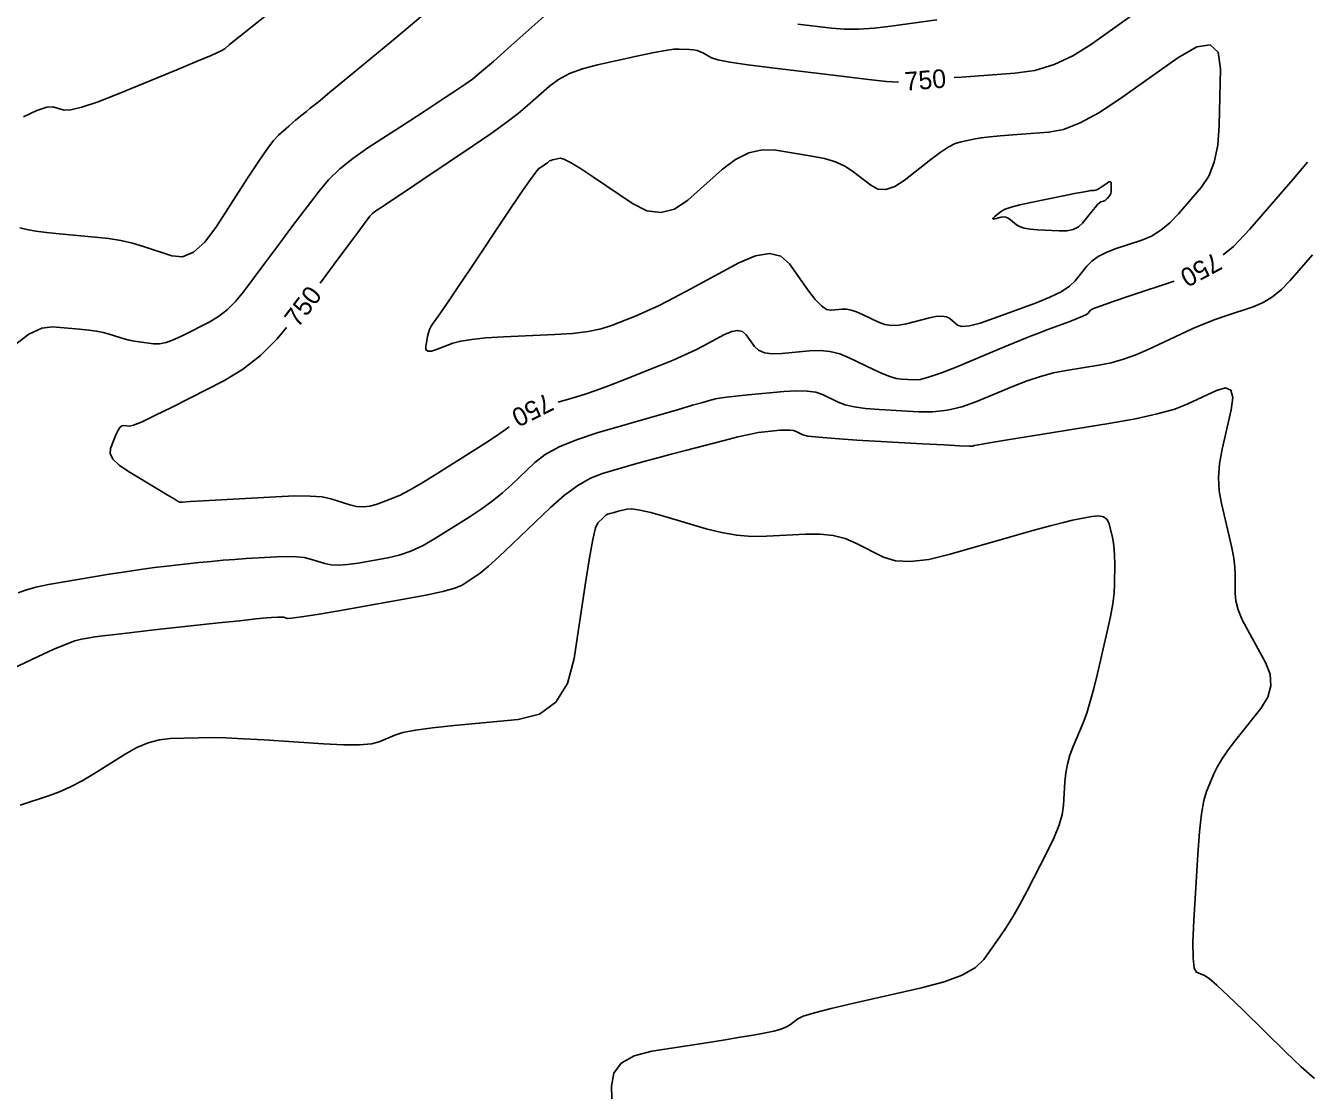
# Model space of a CAD drawing. Extents: x 2079879 to 2092887, y 778083 to 784051.
# Drawn here: x 2084295.6 to 2084488.3, y 780660.6 to 780820.8 of the extents above; entities that cross this region are included whole.
import ezdxf

# ---------------------------------------------------------------- set-up
doc = ezdxf.new("R2010")
doc.units = 0
doc.layers.add('DT_X_Contour_Major', color=7, linetype='Continuous')
doc.layers.add('DT_X_Contour_Minor', color=7, linetype='Continuous')

msp = doc.modelspace()

# ---------------------------------------------------------------- linework, layer by layer
at = {"layer": 'DT_X_Contour_Major'}
for points in [[(2084463.32, 780823.29), (2084455.96, 780818.03), (2084453.16, 780816.28), (2084450.31, 780814.96), (2084447.4, 780814.09), (2084444.42, 780813.66), (2084436.4, 780813.09), (2084435.3, 780813.01)], [(2084426.93, 780812.32), (2084425.13, 780812.45), (2084422.39, 780812.74), (2084418.76, 780813.16), (2084407.88, 780814.47), (2084404.26, 780814.93), (2084401.54, 780815.34), (2084399.72, 780815.69), (2084398.81, 780815.98), (2084397.59, 780816.67), (2084397.12, 780816.9), (2084396.61, 780817.07), (2084396.08, 780817.18), (2084395.5, 780817.24), (2084393.94, 780817.31), (2084393.13, 780817.27), (2084391.86, 780817.09), (2084390.15, 780816.78), (2084387.99, 780816.33), (2084381.63, 780814.94), (2084379.39, 780814.35), (2084377.44, 780813.61), (2084375.78, 780812.73), (2084374.41, 780811.71), (2084371.13, 780808.79), (2084369.7, 780807.59), (2084367.87, 780806.19), (2084365.62, 780804.58), (2084362.98, 780802.77), (2084355.38, 780797.67), (2084352.85, 780795.97), (2084350.96, 780794.7), (2084349.71, 780793.87), (2084349.09, 780793.46), (2084348.31, 780792.95), (2084348.04, 780792.76), (2084347.79, 780792.56), (2084347.58, 780792.36), (2084347.41, 780792.15), (2084346.98, 780791.59), (2084346.56, 780791.02), (2084345.59, 780789.72), (2084344.08, 780787.69), (2084342.03, 780784.93), (2084339.93, 780782.09)], [(2084486.28, 780797.73), (2084488.42, 780800.3)], [(2084475.75, 780786.35), (2084477.29, 780787.61), (2084479.78, 780790.2), (2084486.28, 780797.73)], [(2084375.73, 780764.17), (2084377.99, 780764.83), (2084379.62, 780765.33), (2084381.39, 780765.93), (2084383.3, 780766.63), (2084385.35, 780767.43), (2084391.01, 780769.69), (2084393.01, 780770.51), (2084394.78, 780771.28), (2084396.31, 780771.99), (2084397.6, 780772.65), (2084400.73, 780774.34), (2084401.82, 780774.81), (2084402.72, 780774.96), (2084403.46, 780774.78), (2084404.01, 780774.29), (2084405.26, 780772.53), (2084405.86, 780771.97), (2084406.75, 780771.61), (2084407.91, 780771.46), (2084409.35, 780771.51), (2084413.55, 780771.91), (2084415.11, 780771.96), (2084416.61, 780771.8), (2084418.07, 780771.43), (2084419.48, 780770.86), (2084423.17, 780769.06), (2084424.47, 780768.46), (2084425.6, 780768.02), (2084426.57, 780767.74), (2084427.37, 780767.62), (2084429.29, 780767.51), (2084430.22, 780767.6), (2084431.58, 780767.96), (2084433.36, 780768.57), (2084435.57, 780769.45), (2084442.02, 780772.14), (2084444.3, 780773.08), (2084446.28, 780773.89), (2084447.96, 780774.55), (2084449.36, 780775.08), (2084452.69, 780776.31), (2084453.8, 780776.74), (2084454.63, 780777.09), (2084455.18, 780777.36), (2084455.45, 780777.56), (2084455.79, 780777.99), (2084456.26, 780778.24), (2084457.4, 780778.69), (2084459.21, 780779.34), (2084461.7, 780780.18), (2084468.4, 780782.4)], [(2084334.86, 780775.4), (2084333.47, 780773.7), (2084330.93, 780771.19), (2084328.24, 780769.09), (2084325.41, 780767.4), (2084317.65, 780763.44), (2084315.07, 780762.15), (2084313.14, 780761.23), (2084311.86, 780760.7), (2084311.23, 780760.55), (2084310.41, 780760.66), (2084310.11, 780760.6), (2084309.8, 780760.34), (2084309.5, 780759.88), (2084309.19, 780759.23), (2084308.38, 780757.22), (2084308.32, 780756.44), (2084308.75, 780755.6), (2084309.67, 780754.7), (2084311.08, 780753.74), (2084315.48, 780751.09), (2084316.92, 780750.23), (2084317.96, 780749.61), (2084318.58, 780749.24), (2084318.8, 780749.11), (2084318.82, 780749.12), (2084318.83, 780749.12), (2084318.83, 780749.12), (2084318.84, 780749.12), (2084318.84, 780749.12), (2084318.85, 780749.12), (2084319.23, 780749.14), (2084320.39, 780749.21), (2084322.32, 780749.32), (2084325.02, 780749.47), (2084333.25, 780749.94), (2084336.09, 780750.06), (2084338.41, 780750.04), (2084340.23, 780749.9), (2084341.55, 780749.63), (2084344.37, 780748.73), (2084345.41, 780748.48), (2084346.43, 780748.4), (2084347.41, 780748.5), (2084348.36, 780748.76), (2084350.85, 780749.7), (2084351.95, 780750.18), (2084353.38, 780750.93), (2084355.13, 780751.95), (2084357.22, 780753.23), (2084363.21, 780757.01), (2084365.23, 780758.3), (2084366.81, 780759.34), (2084367.93, 780760.14), (2084368.35, 780760.48)]]:
    msp.add_lwpolyline(points, dxfattribs=at)
at = {"layer": 'DT_X_Contour_Minor'}
for points in [[(2084374.48, 780823.02), (2084368.15, 780817.37), (2084365.98, 780815.45), (2084364.2, 780813.92), (2084362.82, 780812.8), (2084361.83, 780812.07), (2084359.72, 780810.66), (2084358.74, 780810), (2084357.35, 780809.09), (2084355.58, 780807.93), (2084353.4, 780806.52), (2084347.08, 780802.42), (2084344.84, 780800.86), (2084342.88, 780799.26), (2084341.18, 780797.62), (2084339.76, 780795.94), (2084336.33, 780791.41), (2084335.07, 780789.73), (2084333.83, 780788.08), (2084332.63, 780786.48), (2084331.46, 780784.91), (2084328.39, 780780.77), (2084327.2, 780779.32), (2084325.94, 780778.08), (2084324.61, 780777.04), (2084323.2, 780776.2), (2084319.34, 780774.23), (2084317.98, 780773.59), (2084316.77, 780773.17), (2084315.73, 780772.96), (2084314.85, 780772.96), (2084312.71, 780773.24), (2084311.92, 780773.36), (2084311.17, 780773.51), (2084310.46, 780773.68), (2084309.79, 780773.88), (2084308.04, 780774.46), (2084307.28, 780774.67), (2084306.3, 780774.86), (2084305.11, 780775.02), (2084303.71, 780775.17), (2084299.68, 780775.53), (2084298.03, 780775.31), (2084296.12, 780774.39), (2084293.93, 780772.75)], [(2084355.11, 780822.22), (2084352.85, 780820.3), (2084350.39, 780818.26), (2084343.58, 780812.63), (2084341.31, 780810.75), (2084339.6, 780809.34), (2084338.44, 780808.39), (2084337.85, 780807.91), (2084337, 780807.25), (2084336.65, 780806.96), (2084336.23, 780806.61), (2084335.75, 780806.2), (2084335.2, 780805.72), (2084333.63, 780804.35), (2084332.9, 780803.56), (2084331.88, 780802.21), (2084330.57, 780800.31), (2084328.97, 780797.86), (2084324.31, 780790.58), (2084322.58, 780788.26), (2084320.89, 780786.76), (2084319.23, 780786.06), (2084317.62, 780786.19), (2084313.35, 780787.6), (2084311.7, 780788.08), (2084309.94, 780788.48), (2084308.07, 780788.79), (2084306.09, 780789.02), (2084300.66, 780789.51), (2084298.77, 780789.7), (2084297.15, 780789.91), (2084295.82, 780790.14), (2084294.76, 780790.39)], [(2084332.09, 780822.59), (2084329.7, 780820.7), (2084327.92, 780819.3), (2084326.76, 780818.37), (2084326.21, 780817.92), (2084325.57, 780817.35), (2084324.94, 780817), (2084323.53, 780816.35), (2084321.34, 780815.41), (2084318.37, 780814.18), (2084309.42, 780810.51), (2084306.4, 780809.33), (2084304.06, 780808.54), (2084302.4, 780808.14), (2084301.42, 780808.12), (2084299.72, 780808.6), (2084298.8, 780808.55), (2084297.32, 780808.06), (2084295.28, 780807.13)], [(2084432.66, 780821.7), (2084425.77, 780820.73), (2084423.27, 780820.44), (2084420.95, 780820.3), (2084418.8, 780820.3), (2084416.82, 780820.46), (2084411.77, 780821.07)], [(2084475.34, 780814.32), (2084474.99, 780816.82), (2084473.8, 780817.93), (2084471.77, 780817.66), (2084468.91, 780816.01), (2084460.16, 780809.76), (2084457.04, 780807.69), (2084454.22, 780806.18), (2084451.72, 780805.21), (2084449.53, 780804.79), (2084444.1, 780804.4), (2084442.22, 780804.25), (2084440.65, 780804.1), (2084439.39, 780803.95), (2084438.44, 780803.79), (2084436.34, 780803.36), (2084435.46, 780803.07), (2084434.4, 780802.53), (2084433.17, 780801.73), (2084431.77, 780800.68), (2084427.78, 780797.54), (2084426.35, 780796.61), (2084425.03, 780796.17), (2084423.82, 780796.24), (2084422.74, 780796.8), (2084419.99, 780798.95), (2084418.84, 780799.7), (2084417.43, 780800.33), (2084415.77, 780800.83), (2084413.87, 780801.21), (2084408.44, 780802.07), (2084406.42, 780802.13), (2084404.41, 780801.68), (2084402.42, 780800.71), (2084400.45, 780799.22), (2084395.22, 780794.56), (2084393.23, 780793.22), (2084391.18, 780792.69), (2084389.07, 780792.97), (2084386.9, 780794.06), (2084381.05, 780798.04), (2084379.09, 780799.33), (2084377.59, 780800.24), (2084376.57, 780800.76), (2084376.01, 780800.88), (2084375.14, 780800.69), (2084374.85, 780800.62), (2084374.61, 780800.55), (2084374.44, 780800.48), (2084374.33, 780800.4), (2084374.11, 780800.21), (2084374.01, 780800.13), (2084373.87, 780800.02), (2084373.69, 780799.89), (2084373.47, 780799.74), (2084372.83, 780799.31), (2084372.36, 780798.78), (2084371.42, 780797.5), (2084370.02, 780795.48), (2084368.15, 780792.71), (2084362.56, 780784.33), (2084360.68, 780781.52), (2084359.26, 780779.4), (2084358.27, 780777.95), (2084357.74, 780777.18), (2084356.9, 780776.04), (2084356.61, 780775.59), (2084356.38, 780775.11), (2084356.2, 780774.59), (2084356.07, 780774.04), (2084355.8, 780772.53), (2084355.83, 780772.08), (2084356.11, 780771.85), (2084356.65, 780771.86), (2084357.44, 780772.09), (2084359.89, 780773.03), (2084361.06, 780773.35), (2084362.71, 780773.62), (2084364.86, 780773.83), (2084367.5, 780773.98), (2084375.2, 780774.33), (2084377.9, 780774.51), (2084380.23, 780774.8), (2084382.18, 780775.19), (2084383.76, 780775.69), (2084387.47, 780777.17), (2084389.03, 780777.84), (2084390.91, 780778.74), (2084393.13, 780779.86), (2084395.68, 780781.21), (2084402.91, 780785.12), (2084405.42, 780786.21), (2084407.52, 780786.55), (2084409.21, 780786.14), (2084410.5, 780784.99), (2084413.38, 780780.92), (2084414.4, 780779.6), (2084415.31, 780778.67), (2084416.1, 780778.13), (2084416.78, 780777.99), (2084418.43, 780778.15), (2084419.09, 780778.15), (2084419.81, 780778.02), (2084420.61, 780777.76), (2084421.48, 780777.38), (2084423.89, 780776.2), (2084424.84, 780775.86), (2084425.86, 780775.7), (2084426.96, 780775.74), (2084428.13, 780775.96), (2084431.37, 780776.82), (2084432.48, 780777.05), (2084433.4, 780777.12), (2084434.12, 780777.01), (2084434.64, 780776.74), (2084435.77, 780775.78), (2084436.44, 780775.58), (2084437.58, 780775.67), (2084439.2, 780776.08), (2084441.3, 780776.79), (2084447.53, 780779.09), (2084449.66, 780779.95), (2084451.36, 780780.79), (2084452.65, 780781.62), (2084453.51, 780782.45), (2084455.25, 780784.62), (2084456.01, 780785.4), (2084456.97, 780786.09), (2084458.15, 780786.71), (2084459.53, 780787.24), (2084463.5, 780788.55), (2084464.96, 780789.17), (2084466.37, 780790.03), (2084467.73, 780791.15), (2084469.04, 780792.51), (2084472.46, 780796.47), (2084473.59, 780798.17), (2084474.42, 780800.3), (2084474.94, 780802.85), (2084475.16, 780805.82), (2084475.34, 780814.32)], [(2084454.59, 780791.11), (2084453.97, 780790.54), (2084453.18, 780790.15), (2084452.22, 780789.95), (2084451.08, 780789.93), (2084447.81, 780790.12), (2084446.7, 780790.22), (2084445.81, 780790.37), (2084445.13, 780790.58), (2084444.68, 780790.85), (2084443.76, 780791.62), (2084443.41, 780791.87), (2084443.07, 780792.01), (2084442.72, 780792.06), (2084442.37, 780792.02), (2084441.43, 780791.77), (2084441.17, 780791.73), (2084441.09, 780791.77), (2084441.18, 780791.92), (2084441.45, 780792.15), (2084442.4, 780792.9), (2084442.95, 780793.2), (2084443.86, 780793.52), (2084445.15, 780793.86), (2084446.81, 780794.22), (2084451.73, 780795.22), (2084453.37, 780795.55), (2084454.6, 780795.79), (2084455.42, 780795.94), (2084455.83, 780796), (2084456.37, 780796.04), (2084456.58, 780796.08), (2084456.83, 780796.18), (2084457.11, 780796.33), (2084457.42, 780796.53), (2084458.29, 780797.15), (2084458.57, 780797.32), (2084458.77, 780797.34), (2084458.89, 780797.23), (2084458.92, 780796.98), (2084458.91, 780796.14), (2084458.89, 780795.85), (2084458.83, 780795.59), (2084458.75, 780795.38), (2084458.64, 780795.22), (2084458.3, 780794.82), (2084458.17, 780794.69), (2084458.04, 780794.58), (2084457.9, 780794.49), (2084457.75, 780794.43), (2084457.36, 780794.3), (2084457.16, 780794.17), (2084456.87, 780793.9), (2084456.49, 780793.46), (2084456, 780792.88), (2084454.59, 780791.11)], [(2084294.5, 780735.46), (2084295.62, 780735.88), (2084297.14, 780736.31), (2084299.07, 780736.73), (2084301.4, 780737.15), (2084308.17, 780738.27), (2084310.62, 780738.66), (2084312.89, 780739), (2084314.98, 780739.28), (2084316.88, 780739.5), (2084321.73, 780740.03), (2084323.54, 780740.21), (2084325.32, 780740.37), (2084327.07, 780740.51), (2084328.81, 780740.62), (2084333.39, 780740.88), (2084335, 780740.94), (2084336.38, 780740.9), (2084337.53, 780740.78), (2084338.46, 780740.56), (2084340.63, 780739.88), (2084341.55, 780739.69), (2084342.69, 780739.64), (2084344.05, 780739.72), (2084345.62, 780739.95), (2084350.11, 780740.73), (2084351.82, 780741.13), (2084353.58, 780741.77), (2084355.4, 780742.62), (2084357.26, 780743.7), (2084362.31, 780746.88), (2084364.13, 780748.08), (2084365.81, 780749.29), (2084367.33, 780750.52), (2084368.71, 780751.75), (2084372.2, 780755.08), (2084373.77, 780756.29), (2084375.86, 780757.44), (2084378.47, 780758.52), (2084381.6, 780759.54), (2084390.64, 780762.17), (2084393.66, 780763.04), (2084395.93, 780763.7), (2084397.47, 780764.14), (2084398.26, 780764.35), (2084399.39, 780764.65), (2084400.01, 780764.76), (2084401.03, 780764.91), (2084402.46, 780765.07), (2084404.29, 780765.25), (2084409.69, 780765.77), (2084411.58, 780765.88), (2084413.17, 780765.84), (2084414.48, 780765.65), (2084415.5, 780765.3), (2084417.84, 780764.16), (2084418.88, 780763.77), (2084420.26, 780763.45), (2084421.97, 780763.21), (2084424.01, 780763.05), (2084429.9, 780762.71), (2084432.1, 780762.71), (2084434.28, 780762.96), (2084436.43, 780763.47), (2084438.55, 780764.22), (2084444.19, 780766.58), (2084446.27, 780767.39), (2084448.29, 780768.05), (2084450.24, 780768.57), (2084452.12, 780768.94), (2084457.06, 780769.74), (2084458.91, 780770.11), (2084460.76, 780770.63), (2084462.61, 780771.28), (2084464.45, 780772.08), (2084469.37, 780774.41), (2084471.17, 780775.24), (2084472.9, 780775.97), (2084474.56, 780776.62), (2084476.14, 780777.18), (2084480.24, 780778.54), (2084481.75, 780779.16), (2084483.18, 780780.03), (2084484.55, 780781.13), (2084485.84, 780782.47), (2084489.2, 780786.36)], [(2084290.88, 780722.81), (2084297.49, 780725.91), (2084299.75, 780726.94), (2084301.59, 780727.72), (2084303.01, 780728.23), (2084304.01, 780728.49), (2084306.09, 780728.84), (2084307.23, 780729), (2084309.08, 780729.23), (2084311.65, 780729.52), (2084314.93, 780729.89), (2084324.62, 780730.94), (2084327.84, 780731.28), (2084330.24, 780731.54), (2084331.83, 780731.7), (2084332.59, 780731.77), (2084333.53, 780731.82), (2084333.86, 780731.83), (2084334.15, 780731.82), (2084334.39, 780731.8), (2084334.58, 780731.75), (2084335.02, 780731.61), (2084335.63, 780731.65), (2084337.11, 780731.85), (2084339.47, 780732.23), (2084342.71, 780732.79), (2084352.52, 780734.5), (2084355.82, 780735.11), (2084358.38, 780735.68), (2084360.19, 780736.19), (2084361.26, 780736.65), (2084363.11, 780737.82), (2084363.98, 780738.46), (2084365.23, 780739.5), (2084366.84, 780740.95), (2084368.82, 780742.81), (2084374.58, 780748.3), (2084376.68, 780750.16), (2084378.69, 780751.64), (2084380.58, 780752.73), (2084382.37, 780753.43), (2084387, 780754.77), (2084388.8, 780755.28), (2084390.7, 780755.81), (2084392.73, 780756.36), (2084394.86, 780756.91), (2084400.71, 780758.42), (2084402.74, 780758.93), (2084404.43, 780759.31), (2084405.79, 780759.58), (2084406.81, 780759.72), (2084409.08, 780759.94), (2084409.88, 780759.98), (2084410.55, 780759.97), (2084411.1, 780759.89), (2084411.53, 780759.74), (2084412.51, 780759.26), (2084413.29, 780759.07), (2084414.91, 780758.88), (2084417.36, 780758.68), (2084420.65, 780758.47), (2084430.52, 780757.91), (2084433.76, 780757.73), (2084436.11, 780757.61), (2084437.55, 780757.55), (2084438.09, 780757.56), (2084438.31, 780757.65), (2084438.93, 780757.77), (2084440.59, 780758.05), (2084443.32, 780758.5), (2084447.09, 780759.11), (2084458.57, 780760.97), (2084462.54, 780761.68), (2084465.84, 780762.4), (2084468.46, 780763.14), (2084470.42, 780763.9), (2084474.74, 780765.94), (2084476.09, 780766.34), (2084476.92, 780765.98), (2084477.21, 780764.87), (2084476.97, 780763.02), (2084475.61, 780757.08), (2084475.22, 780754.89), (2084475.07, 780752.81), (2084475.16, 780750.82), (2084475.49, 780748.92), (2084476.67, 780743.98), (2084477.06, 780742.23), (2084477.34, 780740.68), (2084477.5, 780739.33), (2084477.55, 780738.19), (2084477.54, 780735.39), (2084477.66, 780734.25), (2084478.02, 780732.93), (2084478.63, 780731.42), (2084479.49, 780729.74), (2084482.11, 780724.99), (2084482.8, 780723.22), (2084482.91, 780721.48), (2084482.45, 780719.77), (2084481.4, 780718.08), (2084477.85, 780713.62), (2084476.63, 780712.03), (2084475.64, 780710.6), (2084474.88, 780709.35), (2084474.35, 780708.26), (2084473.24, 780705.57), (2084472.84, 780704.22), (2084472.5, 780702.2), (2084472.2, 780699.49), (2084471.95, 780696.11), (2084471.34, 780686.18), (2084471.19, 780682.9), (2084471.22, 780680.5), (2084471.41, 780679), (2084471.76, 780678.37), (2084472.94, 780677.89), (2084473.63, 780677.43), (2084474.81, 780676.42), (2084476.5, 780674.85), (2084478.69, 780672.73), (2084485.2, 780666.33), (2084487.48, 780664.14), (2084489.47, 780662.37)], [(2084294.78, 780703.53), (2084299.08, 780704.94), (2084300.72, 780705.55), (2084302.39, 780706.29), (2084304.11, 780707.19), (2084305.86, 780708.23), (2084310.6, 780711.2), (2084312.35, 780712.18), (2084314.06, 780712.9), (2084315.73, 780713.35), (2084317.36, 780713.54), (2084321.63, 780713.68), (2084323.45, 780713.7), (2084325.71, 780713.65), (2084328.39, 780713.53), (2084331.51, 780713.35), (2084340.4, 780712.75), (2084343.42, 780712.6), (2084345.83, 780712.61), (2084347.63, 780712.76), (2084348.81, 780713.07), (2084351.14, 780714.08), (2084352.36, 780714.45), (2084354.25, 780714.82), (2084356.83, 780715.17), (2084360.09, 780715.51), (2084369.68, 780716.4), (2084372.9, 780717.23), (2084375.39, 780719.04), (2084377.14, 780721.83), (2084378.14, 780725.6), (2084379.84, 780736.96), (2084380.43, 780740.72), (2084380.93, 780743.48), (2084381.34, 780745.25), (2084381.67, 780746.02), (2084382.42, 780746.73), (2084382.68, 780746.97), (2084382.88, 780747.14), (2084383.04, 780747.26), (2084383.15, 780747.31), (2084383.37, 780747.38), (2084383.51, 780747.42), (2084383.76, 780747.48), (2084384.13, 780747.58), (2084384.61, 780747.7), (2084386.04, 780748.07), (2084386.8, 780748.11), (2084388.01, 780747.93), (2084389.67, 780747.56), (2084391.77, 780746.97), (2084397.99, 780745.13), (2084400.3, 780744.54), (2084402.59, 780744.15), (2084404.85, 780743.97), (2084407.08, 780743.99), (2084412.99, 780744.31), (2084415.12, 780744.31), (2084417.09, 780744.09), (2084418.89, 780743.64), (2084420.52, 780742.97), (2084424.65, 780740.85), (2084426.44, 780740.29), (2084428.71, 780740.17), (2084431.46, 780740.5), (2084434.69, 780741.28), (2084443.96, 780743.95), (2084447.14, 780744.86), (2084449.72, 780745.57), (2084451.71, 780746.07), (2084453.1, 780746.39), (2084456.02, 780746.96), (2084457, 780747.05), (2084457.76, 780746.89), (2084458.28, 780746.49), (2084458.58, 780745.84), (2084459.08, 780743.78), (2084459.24, 780742.95), (2084459.35, 780742.03), (2084459.42, 780741.01), (2084459.44, 780739.89), (2084459.42, 780736.77), (2084459.35, 780735.45), (2084459.14, 780733.83), (2084458.8, 780731.9), (2084458.32, 780729.68), (2084456.86, 780723.33), (2084456.32, 780721.09), (2084455.77, 780719.1), (2084455.22, 780717.38), (2084454.67, 780715.91), (2084453.2, 780712.37), (2084452.71, 780711.03), (2084452.33, 780709.7), (2084452.08, 780708.37), (2084451.94, 780707.05), (2084451.72, 780703.5), (2084451.51, 780702.07), (2084451.03, 780700.42), (2084450.29, 780698.55), (2084449.28, 780696.48), (2084446.26, 780690.65), (2084445.15, 780688.58), (2084444.1, 780686.74), (2084443.11, 780685.12), (2084442.18, 780683.72), (2084439.77, 780680.3), (2084438.5, 780679.07), (2084436.51, 780677.95), (2084433.79, 780676.93), (2084430.35, 780676.02), (2084420.19, 780673.72), (2084416.81, 780672.93), (2084414.27, 780672.27), (2084412.59, 780671.75), (2084411.75, 780671.36), (2084410.65, 780670.5), (2084410.18, 780670.2), (2084409.61, 780669.94), (2084408.93, 780669.71), (2084408.14, 780669.53), (2084405.89, 780669.08), (2084404.77, 780668.88), (2084403.09, 780668.59), (2084400.85, 780668.23), (2084398.04, 780667.78), (2084389.82, 780666.48), (2084387.13, 780665.79), (2084385.22, 780664.69), (2084384.1, 780663.17), (2084383.76, 780661.24), (2084383.91, 780655.56)]]:
    msp.add_lwpolyline(points, dxfattribs=at)

# ---------------------------------------------------------------- texts
at = {"layer": 'DT_X_Contour_Major'}
for rotation, p in [(4.6963, (2084427.95, 780811.02)), (208.2752, (2084474.51, 780786.79)), (52.8879, (2084336.56, 780775.26)), (206.5441, (2084374.04, 780765.62))]:
    msp.add_text('750', height=2.8, rotation=rotation, dxfattribs=at).set_placement(p)

doc.saveas('drawing.dxf')
